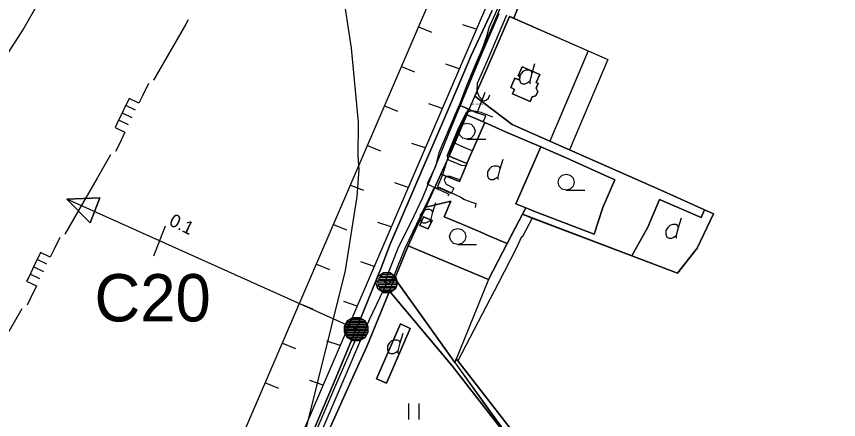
# Model space of a CAD drawing. Extents: x -645676 to -642474, y -1077513 to -1072613.
# Drawn here: x -643719.5 to -643337.9, y -1075036 to -1074848.6 of the extents above; entities that cross this region are included whole.
import ezdxf

# ---------------------------------------------------------------- set-up
doc = ezdxf.new("R2010")
doc.units = 0
for name, color, linetype in [('KN', 7, 'Continuous'), ('KULTURY_STAV', 7, 'Continuous'), ('KULTURY_ZNACKY', 7, 'Continuous'), ('M_stn__komunikace', 7, 'Continuous'), ('NERESENE_POZEMKY', 7, 'Continuous'), ('Obvod_KP_', 7, 'Continuous'), ('OBVOD_PU', 7, 'Continuous'), ('P__kop___st_vaj_c_', 7, 'Continuous'), ('PC_NAVRH', 7, 'Continuous'), ('PC_POPIS_NAVRH', 7, 'Continuous'), ('PC_STAN_NAVRH', 7, 'Continuous'), ('PC_STAN_STAV', 7, 'Continuous'), ('PC_STAV', 7, 'Continuous'), ('PLYNOVOD', 7, 'Continuous'), ('SDELOVACI', 7, 'Continuous'), ('USES_BK_NAVRH', 7, 'Continuous'), ('VRSTEVNICE', 7, 'Continuous')]:
    doc.layers.add(name, color=color, linetype=linetype)

# ---------------------------------------------------------------- blocks, each defined once
blk = doc.blocks.new('$437')
blk.add_lwpolyline([(0.15, 0.48), (0.4, 0.3), (0.5, 0.01), (0.4, -0.28), (0.15, -0.46), (-0.16, -0.46), (-0.41, -0.28), (-0.51, 0.01), (-0.41, 0.3), (-0.16, 0.48), (0.15, 0.48), (0.2, 0.4), (-0.2, 0.4), (-0.31, 0.32), (0.31, 0.32), (0.36, 0.24), (-0.36, 0.24), (-0.39, 0.16), (0.4, 0.16), (0.45, 0.08), (-0.43, 0.08), (-0.43, 0), (0.45, 0), (0.45, -0.08), (-0.43, -0.08), (-0.38, -0.16), (0.4, -0.16), (0.37, -0.24), (-0.35, -0.24), (-0.29, -0.32), (0.31, -0.32), (0.21, -0.4), (-0.19, -0.4)])
blk = doc.blocks.new('$406')
blk.add_lwpolyline([(-0.19, 0.72), (0.2, 0.72), (0.54, 0.53), (0.73, 0.19), (0.73, -0.2), (0.54, -0.54), (0.2, -0.73), (-0.19, -0.73), (-0.53, -0.54), (-0.72, -0.2), (-0.72, 0.19), (-0.53, 0.53), (-0.2, 0.72), (-0.28, 0.64), (0.28, 0.64), (0.44, 0.56), (-0.44, 0.56), (-0.52, 0.48), (0.52, 0.48), (0.56, 0.4), (-0.55, 0.4), (-0.6, 0.32), (0.6, 0.32), (0.68, 0.24), (-0.59, 0.24), (-0.65, 0.24), (-0.68, 0.16), (0.59, 0.16), (0.68, 0.16), (0.68, 0.08), (-0.59, 0.08), (-0.68, 0.08), (-0.68, 0), (0.59, 0), (0.68, 0), (0.68, -0.08), (-0.59, -0.08), (-0.68, -0.08), (-0.68, -0.16), (0.59, -0.16), (0.68, -0.16), (0.65, -0.24), (-0.62, -0.24), (-0.65, -0.24), (-0.6, -0.32), (0.6, -0.32), (0.56, -0.4), (-0.55, -0.4), (-0.52, -0.48), (0.52, -0.48), (0.44, -0.56), (-0.44, -0.56), (-0.28, -0.64), (0.28, -0.64), (-0.02, -0.69)])
blk = doc.blocks.new('$944')
blk.add_line((0, 1.5), (0, -1.5))
blk = doc.blocks.new('$920')
for points in [[(0, 0), (-2.8, 1.25), (-2.8, -1.25), (0, 0)], [(-2.8, 1.25), (0, 0), (-2.8, -1.25), (-2.8, 1.25)]]:
    blk.add_lwpolyline(points)
blk = doc.blocks.new('3$0400')
blk.add_lwpolyline([(0, 0), (-0.38, 0.1), (-0.65, 0.38), (-0.75, 0.75), (-0.65, 1.12), (-0.38, 1.4), (0, 1.5), (0.38, 1.4), (0.65, 1.12), (0.75, 0.75), (0.65, 0.38), (0.38, 0.1), (0, 0), (1.75, 0)])
blk = doc.blocks.new('$431')
blk.add_line((0.63, 0.99), (0.9, 1.89))
blk.add_lwpolyline([(0.45, 0), (0.45, 0.27), (0.63, 0.99), (0.54, 1.17), (0.36, 1.26), (0.09, 1.26), (-0.18, 1.17), (-0.36, 0.99), (-0.54, 0.72), (-0.54, 0.36), (-0.45, 0.09), (-0.27, 0), (0, 0), (0.18, 0.09), (0.45, 0.27)])
blk = doc.blocks.new('3$0600')
for p, q in [((-0.5, 1.5), (-0.5, 0)), ((0.5, 0), (0.5, 1.5))]:
    blk.add_line(p, q)
blk = doc.blocks.new('2$1030')
blk.add_line((0, 0), (0, -0.5))
blk = doc.blocks.new('6$3520')
for p, q in [((-0.76, 0), (-0.76, -1)), ((0, -1), (0, 0)), ((0.76, 0), (0.76, -1))]:
    blk.add_line(p, q)
blk.add_lwpolyline([(-3.5, 0), (-2.23, 0), (-1.48, 0), (-1.48, -1), (-0.21, -1), (1.06, -1), (1.5, -1), (1.5, 0), (2.77, 0), (3.5, 0)])

msp = doc.modelspace()

# ---------------------------------------------------------------- linework, layer by layer
at = {"layer": 'KN'}
msp.add_lwpolyline([(-643687.88, -1074804.66), (-643716.17, -1074854.15), (-643740.1, -1074891.11)], dxfattribs=at)
at = {"layer": 'KULTURY_STAV'}
for points in [[(-643478.45, -1074823.5), (-643488.73, -1074849.53), (-643490.75, -1074848.65), (-643500.55, -1074871.65), (-643506.75, -1074885.77), (-643489.5, -1074898.81), (-643471.96, -1074906.61), (-643462.8, -1074910.67), (-643419.43, -1074929.92), (-643400.22, -1074938.56), (-643401.77, -1074942.08), (-643421.02, -1074933.66), (-643426.53, -1074946.56), (-643432.36, -1074957.15), (-643433.93, -1074959.91), (-643480.12, -1074942.36), (-643484.72, -1074940.61), (-643483.17, -1074937.63), (-643478.59, -1074939.48), (-643451.33, -1074949.84), (-643447.33, -1074937.5), (-643441.73, -1074924.6), (-643464.34, -1074914.32), (-643476.16, -1074909.27), (-643492.61, -1074902.23), (-643502.18, -1074897.96), (-643510.44, -1074894.34), (-643518.71, -1074913.6), (-643510.41, -1074917.06), (-643510.79, -1074917.94), (-643513.96, -1074925.32), (-643522.51, -1074921.95), (-643529.49, -1074937.27), (-643537.7, -1074955.3), (-643543.93, -1074970.42), (-643527.22, -1074993.86), (-643516.08, -1075009.48), (-643515.41, -1075007.84), (-643514.63, -1075008.76), (-643478.55, -1075055.17)], [(-643478.55, -1075055.17), (-643514.63, -1075008.76), (-643515.41, -1075007.84), (-643516.08, -1075009.48), (-643527.22, -1074993.86), (-643543.93, -1074970.42), (-643537.7, -1074955.3), (-643500.46, -1074970.88), (-643491.76, -1074954.15), (-643489.24, -1074949.31), (-643484.72, -1074940.61), (-643480.12, -1074942.36), (-643433.93, -1074959.91), (-643412.65, -1074967.96), (-643403.55, -1074956.38), (-643396.05, -1074940.35), (-643400.22, -1074938.56), (-643419.43, -1074929.92), (-643462.8, -1074910.67), (-643471.96, -1074906.61), (-643489.5, -1074898.81), (-643506.75, -1074885.77), (-643500.55, -1074871.65), (-643490.75, -1074848.65), (-643488.73, -1074849.53), (-643478.45, -1074823.5)], [(-643582.48, -1075042.91), (-643572.34, -1075019.19), (-643561.84, -1074993.96), (-643561.59, -1074993.34), (-643560.36, -1074990.3), (-643550.3, -1074965.44), (-643546.14, -1074954.43), (-643535.97, -1074931.14), (-643530.69, -1074918.84), (-643521.31, -1074896.96), (-643514.06, -1074879.93), (-643508.45, -1074866.74), (-643498.78, -1074845.95)], [(-643498.78, -1074845.95), (-643508.45, -1074866.74), (-643514.06, -1074879.93), (-643521.31, -1074896.96), (-643530.69, -1074918.84), (-643535.97, -1074931.14), (-643546.14, -1074954.43), (-643550.3, -1074965.44), (-643560.36, -1074990.3), (-643561.59, -1074993.34), (-643561.84, -1074993.96), (-643572.34, -1075019.19), (-643582.48, -1075042.91)], [(-643484.76, -1074872.03), (-643476.64, -1074875.64), (-643478.27, -1074879.34), (-643477.37, -1074879.76), (-643478.33, -1074881.98), (-643477.51, -1074883.52), (-643478.43, -1074885.57), (-643480.13, -1074886.01), (-643481.09, -1074888.2), (-643489.25, -1074884.57), (-643488.34, -1074882.55), (-643489.82, -1074881.88), (-643490.11, -1074881.71), (-643488.19, -1074877.39), (-643486.42, -1074878.19), (-643485.76, -1074876.72), (-643486.64, -1074876.3), (-643484.76, -1074872.03)], [(-643484.76, -1074872.03), (-643486.64, -1074876.3), (-643485.76, -1074876.72), (-643486.42, -1074878.19), (-643488.19, -1074877.39), (-643490.11, -1074881.71), (-643489.82, -1074881.88), (-643488.34, -1074882.55), (-643489.25, -1074884.57), (-643481.09, -1074888.2), (-643480.13, -1074886.01), (-643478.43, -1074885.57), (-643477.51, -1074883.52), (-643478.33, -1074881.98), (-643477.37, -1074879.76), (-643478.27, -1074879.34), (-643476.64, -1074875.64), (-643484.76, -1074872.03)], [(-643510.44, -1074894.34), (-643502.18, -1074897.96), (-643510.41, -1074917.06), (-643518.71, -1074913.6), (-643510.44, -1074894.34)], [(-643502.18, -1074897.96), (-643492.61, -1074902.23), (-643476.16, -1074909.27), (-643487.7, -1074935.8), (-643483.17, -1074937.63), (-643484.72, -1074940.61), (-643489.24, -1074949.31), (-643491.76, -1074954.15), (-643500.24, -1074950.57), (-643504.01, -1074948.97), (-643513.15, -1074945.07), (-643520.99, -1074941.73), (-643517.86, -1074934.5), (-643529.49, -1074937.27), (-643522.51, -1074921.95), (-643513.96, -1074925.32), (-643510.79, -1074917.94), (-643510.41, -1074917.06), (-643502.18, -1074897.96)], [(-643476.16, -1074909.27), (-643464.34, -1074914.32), (-643441.73, -1074924.6), (-643447.33, -1074937.5), (-643451.33, -1074949.84), (-643478.59, -1074939.48), (-643483.17, -1074937.63), (-643487.7, -1074935.8), (-643476.16, -1074909.27)], [(-643517.86, -1074934.5), (-643520.99, -1074941.73), (-643513.15, -1074945.07), (-643504.01, -1074948.97), (-643500.24, -1074950.57), (-643491.76, -1074954.15), (-643500.46, -1074970.88), (-643537.7, -1074955.3), (-643529.49, -1074937.27), (-643517.86, -1074934.5)], [(-643421.02, -1074933.66), (-643401.77, -1074942.08), (-643400.22, -1074938.56), (-643396.05, -1074940.35), (-643403.55, -1074956.38), (-643412.65, -1074967.96), (-643433.93, -1074959.91), (-643432.36, -1074957.15), (-643426.53, -1074946.56), (-643421.02, -1074933.66)], [(-643530.53, -1074941.76), (-643532.27, -1074945.74), (-643528.4, -1074947.43), (-643526.63, -1074943.52), (-643530.53, -1074941.76)], [(-643530.53, -1074941.76), (-643526.63, -1074943.52), (-643528.4, -1074947.43), (-643532.27, -1074945.74), (-643530.53, -1074941.76)], [(-643546.39, -1074976.36), (-643517.29, -1075011.03), (-643481.44, -1075057.16), (-643466.38, -1075082.52), (-643468.64, -1075087.39), (-643538.17, -1075056.97), (-643574.53, -1075041.03), (-643562.74, -1075014.92), (-643556.97, -1075002.06), (-643546.39, -1074976.36)], [(-643481.44, -1075057.16), (-643517.29, -1075011.03), (-643546.39, -1074976.36), (-643556.97, -1075002.06), (-643562.74, -1075014.92), (-643574.53, -1075041.03)], [(-643541.28, -1074991.51), (-643536.72, -1074993.6), (-643547.78, -1075019.06), (-643552.38, -1075017.06), (-643541.28, -1074991.51)], [(-643541.28, -1074991.51), (-643552.38, -1075017.06), (-643547.78, -1075019.06), (-643536.72, -1074993.6), (-643541.28, -1074991.51)]]:
    msp.add_lwpolyline(points, dxfattribs=at)
at = {"layer": 'M_stn__komunikace'}
for p, q in [((-643504.52, -1074868.25), (-643495.41, -1074847.21)), ((-643492.01, -1074848.09), (-643501.11, -1074869.21)), ((-643517.08, -1074898.92), (-643504.52, -1074868.25)), ((-643501.11, -1074869.21), (-643505.65, -1074879.85)), ((-643505.65, -1074879.85), (-643505.81, -1074883.27)), ((-643505.81, -1074883.27), (-643504.93, -1074885.72)), ((-643504.93, -1074885.72), (-643502.79, -1074887.96)), ((-643501.5, -1074887.58), (-643500.49, -1074886.61)), ((-643500.49, -1074886.61), (-643499.78, -1074885.02)), ((-643502.79, -1074887.96), (-643501.5, -1074887.58)), ((-643510.73, -1074893.28), (-643514.35, -1074900.43)), ((-643507.98, -1074892.49), (-643510.73, -1074893.28)), ((-643503.89, -1074893.23), (-643507.98, -1074892.49)), ((-643498.49, -1074895.39), (-643503.89, -1074893.23)), ((-643530.87, -1074932.87), (-643517.08, -1074898.92)), ((-643514.35, -1074900.43), (-643519.67, -1074913.34)), ((-643519.67, -1074913.34), (-643519.27, -1074915.14)), ((-643519.27, -1074915.14), (-643513.1, -1074917.75)), ((-643513.1, -1074917.75), (-643510.8, -1074917.94)), ((-643520.23, -1074923.09), (-643521.03, -1074924.74)), ((-643521.03, -1074924.74), (-643520.05, -1074926.62)), ((-643518.17, -1074923.08), (-643520.23, -1074923.09)), ((-643513.7, -1074924.62), (-643518.17, -1074923.08)), ((-643526.04, -1074929.03), (-643528.53, -1074934.28)), ((-643525.09, -1074928.38), (-643526.04, -1074929.03)), ((-643522.78, -1074928.62), (-643525.09, -1074928.38)), ((-643517.76, -1074930.96), (-643522.78, -1074928.62)), ((-643520.05, -1074926.62), (-643516.56, -1074928.41)), ((-643516.56, -1074928.41), (-643517.76, -1074930.96)), ((-643536.26, -1074944.29), (-643530.87, -1074932.87)), ((-643528.53, -1074934.28), (-643533.84, -1074945.22)), ((-643542, -1074955.5), (-643536.26, -1074944.29)), ((-643533.84, -1074945.22), (-643539.23, -1074956.48)), ((-643548.53, -1074972.03), (-643542, -1074955.5)), ((-643539.23, -1074956.48), (-643544.71, -1074970.05)), ((-643544.71, -1074970.05), (-643546.65, -1074973.09)), ((-643546.65, -1074973.09), (-643548.53, -1074972.03))]:
    msp.add_line(p, q, dxfattribs=at)
at = {"layer": 'NERESENE_POZEMKY'}
for points in [[(-643574.53, -1075041.03), (-643562.74, -1075014.92), (-643556.97, -1075002.06), (-643546.39, -1074976.36), (-643545.25, -1074973.62), (-643543.93, -1074970.42), (-643537.7, -1074955.3), (-643529.49, -1074937.27), (-643522.51, -1074921.95), (-643518.71, -1074913.6), (-643510.44, -1074894.34), (-643506.75, -1074885.77), (-643500.55, -1074871.65), (-643490.75, -1074848.65)], [(-643490.75, -1074848.65), (-643488.73, -1074849.53), (-643454.15, -1074864.58), (-643445.05, -1074868.59), (-643462.8, -1074910.67), (-643419.43, -1074929.92), (-643400.22, -1074938.56), (-643396.05, -1074940.35), (-643403.55, -1074956.38), (-643412.65, -1074967.96), (-643433.93, -1074959.91), (-643480.12, -1074942.36), (-643484.74, -1074951.23), (-643485.16, -1074951.12), (-643487.37, -1074956.17), (-643495.99, -1074972.78), (-643514.63, -1075008.76), (-643478.55, -1075055.17)]]:
    msp.add_lwpolyline(points, dxfattribs=at)
at = {"layer": 'Obvod_KP_'}
for points in [[(-643730.15, -1074676.99), (-643712.93, -1074647.72), (-643703.01, -1074630.92), (-643676.88, -1074645.92), (-643687.98, -1074664.87), (-643699.6, -1074684.03), (-643658.16, -1074692.76), (-643652.49, -1074694.77), (-643634.51, -1074700.94), (-643641.64, -1074716), (-643663.42, -1074760), (-643687.88, -1074804.66), (-643716.17, -1074854.15), (-643740.1, -1074891.11)], [(-643574.53, -1075041.03), (-643562.74, -1075014.92), (-643556.97, -1075002.06), (-643545.25, -1074973.62), (-643543.93, -1074970.42), (-643537.7, -1074955.3), (-643529.49, -1074937.27), (-643522.51, -1074921.95), (-643518.71, -1074913.6), (-643517.89, -1074911.68), (-643510.44, -1074894.34), (-643506.75, -1074885.77), (-643500.55, -1074871.65), (-643490.75, -1074848.65), (-643454.15, -1074864.58), (-643463.9, -1074887.67), (-643471.96, -1074906.61), (-643419.43, -1074929.92), (-643400.22, -1074938.56), (-643396.05, -1074940.35), (-643403.55, -1074956.38), (-643412.65, -1074967.96), (-643433.93, -1074959.91), (-643484.72, -1074940.61), (-643491.76, -1074954.15), (-643500.46, -1074970.88), (-643516.08, -1075009.48), (-643490.94, -1075044.62)]]:
    msp.add_lwpolyline(points, dxfattribs=at)
at = {"layer": 'OBVOD_PU'}
for points in [[(-643730.15, -1074676.99), (-643712.93, -1074647.72), (-643703.01, -1074630.92), (-643676.88, -1074645.92), (-643687.98, -1074664.87), (-643699.6, -1074684.03), (-643658.16, -1074692.76), (-643652.49, -1074694.77), (-643634.51, -1074700.94), (-643641.64, -1074716), (-643663.42, -1074760), (-643687.88, -1074804.66), (-643716.17, -1074854.15), (-643740.1, -1074891.11)], [(-643574.53, -1075041.03), (-643562.74, -1075014.92), (-643556.97, -1075002.06), (-643545.25, -1074973.62), (-643543.93, -1074970.42), (-643537.7, -1074955.3), (-643529.49, -1074937.27), (-643518.71, -1074913.6), (-643517.89, -1074911.68), (-643510.44, -1074894.34), (-643506.75, -1074885.77), (-643500.55, -1074871.65), (-643490.75, -1074848.65)], [(-643490.75, -1074848.65), (-643454.15, -1074864.58), (-643471.96, -1074906.61), (-643419.43, -1074929.92), (-643400.22, -1074938.56), (-643396.05, -1074940.35), (-643403.55, -1074956.38), (-643412.65, -1074967.96), (-643484.72, -1074940.61), (-643491.76, -1074954.15), (-643500.46, -1074970.88), (-643516.08, -1075009.48), (-643462, -1075084.28)]]:
    msp.add_lwpolyline(points, dxfattribs=at)
at = {"layer": 'P__kop___st_vaj_c_'}
msp.add_lwpolyline([(-643616.01, -1075125.08), (-643595.06, -1075075.72), (-643571.29, -1075019.94), (-643560.26, -1074994.78)], dxfattribs=at)
at = {"layer": 'PC_NAVRH'}
msp.add_line((-643561.84, -1074993.96), (-643696.1, -1074933.6), dxfattribs=at)
at = {"layer": 'PC_STAV'}
msp.add_lwpolyline([(-643547.63, -1074972.51), (-643555.63, -1074989.35), (-643604.37, -1075103.28), (-643624.41, -1075149.11)], dxfattribs=at)
at = {"layer": 'PLYNOVOD'}
for p, q in [((-643494.35, -1074843.3), (-643510.56, -1074880.72)), ((-643510.56, -1074880.72), (-643512.78, -1074887.6)), ((-643505.26, -1074892.23), (-643503.01, -1074886.72)), ((-643503.01, -1074886.72), (-643501.9, -1074883.89)), ((-643513.97, -1074889.93), (-643515.2, -1074892.37)), ((-643512.78, -1074887.6), (-643513.97, -1074889.93)), ((-643513.97, -1074889.93), (-643513.01, -1074890.32)), ((-643513.01, -1074890.32), (-643512.02, -1074890.72)), ((-643512.02, -1074890.72), (-643505.8, -1074893.51)), ((-643505.8, -1074893.51), (-643512.02, -1074890.72)), ((-643515.2, -1074892.37), (-643523.45, -1074912.05)), ((-643505.8, -1074893.51), (-643505.26, -1074892.23)), ((-643501.66, -1074894.88), (-643505.8, -1074893.51)), ((-643502.1, -1074895.89), (-643501.66, -1074894.88)), ((-643502.85, -1074897.64), (-643502.1, -1074895.89)), ((-643523.45, -1074912.05), (-643525.1, -1074918.34)), ((-643525.1, -1074918.34), (-643528.92, -1074926.5)), ((-643528.92, -1074926.5), (-643524.59, -1074928.54)), ((-643524.59, -1074928.54), (-643523.41, -1074929.09)), ((-643523.41, -1074929.09), (-643523.05, -1074929.26)), ((-643523.05, -1074929.26), (-643518.88, -1074931.21)), ((-643519.09, -1074931.8), (-643519.28, -1074932.24)), ((-643518.88, -1074931.21), (-643519.09, -1074931.8))]:
    msp.add_line(p, q, dxfattribs=at)
for points in [[(-643473.17, -1074784.29), (-643471.97, -1074786.75), (-643471.39, -1074788.95), (-643471.45, -1074790.05), (-643483.17, -1074817.28), (-643494.35, -1074843.3), (-643510.56, -1074880.72), (-643512.78, -1074887.6), (-643513.97, -1074889.93)], [(-643639.81, -1074850.16), (-643640.99, -1074852.27), (-643655.94, -1074878.28)], [(-643513.97, -1074889.93), (-643515.2, -1074892.37), (-643523.45, -1074912.05), (-643525.1, -1074918.34), (-643528.92, -1074926.5), (-643524.59, -1074928.54)], [(-643513.97, -1074889.93), (-643513.01, -1074890.32), (-643512.02, -1074890.72)], [(-643675.88, -1074912.96), (-643682.11, -1074923.8), (-643697.07, -1074949.81)], [(-643717.01, -1074984.48), (-643783.07, -1075099.35), (-643798.43, -1075125.12)]]:
    msp.add_lwpolyline(points, dxfattribs=at)
at = {"layer": 'SDELOVACI'}
for points in [[(-643516.67, -1074907.25), (-643515.04, -1074903.21), (-643511.46, -1074895.22), (-643509.64, -1074891.94), (-643513.87, -1074889.85), (-643512.75, -1074887), (-643510.3, -1074880.36), (-643506.66, -1074871.49), (-643503.28, -1074863.55), (-643501.11, -1074857.43), (-643500.16, -1074853.79), (-643495.79, -1074844.24), (-643492.07, -1074835.9), (-643488.14, -1074826.84), (-643481.47, -1074812.29), (-643477.13, -1074801.57), (-643473.43, -1074792.52), (-643472.22, -1074786.75)], [(-643516.67, -1074907.25), (-643515.04, -1074903.21), (-643511.46, -1074895.22), (-643509.64, -1074891.94), (-643513.87, -1074889.85), (-643512.75, -1074887), (-643510.3, -1074880.36), (-643506.66, -1074871.49), (-643503.28, -1074863.55), (-643501.11, -1074857.43), (-643500.16, -1074853.79), (-643495.79, -1074844.24), (-643492.07, -1074835.9), (-643488.14, -1074826.84), (-643481.47, -1074812.29), (-643477.13, -1074801.57), (-643473.43, -1074792.52), (-643472.22, -1074786.75)], [(-643516.67, -1074907.25), (-643519.55, -1074913.71), (-643519.09, -1074914.27)], [(-643516.67, -1074907.25), (-643519.55, -1074913.71), (-643519.09, -1074914.27)], [(-643516.67, -1074907.25), (-643511.8, -1074909.35), (-643508.91, -1074910.6), (-643507.73, -1074910.79)], [(-643516.67, -1074907.25), (-643511.8, -1074909.35), (-643508.91, -1074910.6), (-643507.73, -1074910.79)], [(-643519.09, -1074914.27), (-643519.43, -1074914.81), (-643521.8, -1074922.23), (-643524.05, -1074927.63), (-643515.9, -1074931.41), (-643513.34, -1074932.65), (-643511.58, -1074933.69), (-643508.16, -1074935.02), (-643506.28, -1074935.64), (-643506.67, -1074937.51)], [(-643519.09, -1074914.27), (-643519.43, -1074914.81), (-643521.8, -1074922.23), (-643524.05, -1074927.63), (-643515.9, -1074931.41), (-643513.34, -1074932.65), (-643511.58, -1074933.69), (-643508.16, -1074935.02), (-643506.28, -1074935.64), (-643506.67, -1074937.51)]]:
    msp.add_lwpolyline(points, dxfattribs=at)
at = {"layer": 'USES_BK_NAVRH'}
msp.add_lwpolyline([(-643140.05, -1074334.77), (-643371.48, -1074723.77), (-643386.93, -1074710.69), (-643471.56, -1074774.24), (-643586.65, -1075041.85), (-643614.85, -1075044.14), (-643491.9, -1074758.24), (-643387.13, -1074679.58), (-643365.02, -1074664.02), (-643154.25, -1074308.76)], dxfattribs=at)
at = {"layer": 'VRSTEVNICE'}
msp.add_lwpolyline([(-643592.44, -1075070.19), (-643566.8, -1074966.79), (-643561.39, -1074932.32), (-643560.4, -1074919.79), (-643560.97, -1074913.52), (-643560.82, -1074897.86), (-643563.96, -1074863.39), (-643571.08, -1074816.39), (-643575.63, -1074797.59), (-643580.48, -1074785.06), (-643595.57, -1074755.72), (-643606.4, -1074738.63), (-643613.66, -1074730.09), (-643623.35, -1074721.54), (-643624.77, -1074717.41), (-643624.48, -1074710.29), (-643625.62, -1074705.02), (-643627.19, -1074702.17), (-643648.13, -1074681.95), (-643661.09, -1074666.57), (-643673.05, -1074649.9), (-643691.28, -1074616.72)], dxfattribs=at)

# ---------------------------------------------------------------- block references
at = {"layer": 'KULTURY_ZNACKY', "xscale": 5, "yscale": 5}
for name, p in [('$431', (-643483.37, -1074879.91)), ('3$0400', (-643510.42, -1074905.7)), ('$431', (-643498.18, -1074924.47)), ('3$0400', (-643464.39, -1074929.46)), ('$431', (-643529.45, -1074944.61)), ('$431', (-643415.35, -1074951.69)), ('3$0400', (-643514.71, -1074954.66)), ('$431', (-643544.55, -1075005.33)), ('3$0600', (-643535.07, -1075035.99))]:
    msp.add_blockref(name, p, dxfattribs=at)
at = {"layer": 'PC_STAN_NAVRH', "xscale": 4.999999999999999, "yscale": 5, "rotation": 158.512054}
for name, p in [('$920', (-643696.1, -1074933.6)), ('$944', (-643653.05, -1074952.96))]:
    msp.add_blockref(name, p, dxfattribs=at)
at = {"layer": 'PC_STAN_NAVRH', "xscale": 7.5, "yscale": 7.5}
msp.add_blockref('$406', (-643561.84, -1074993.96), dxfattribs=at)
at = {"layer": 'PC_STAN_STAV', "xscale": 10, "yscale": 10}
msp.add_blockref('$437', (-643547.63, -1074972.51), dxfattribs=at)
at = {"layer": 'PLYNOVOD', "xscale": 5}
for p, yscale, rotation in [((-643665.91, -1074895.62), 4.999999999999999, -115.702375), ((-643707.04, -1074967.14), 5.000000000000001, -115.71302200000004)]:
    msp.add_blockref('6$3520', p, dxfattribs=dict(at, yscale=yscale, rotation=rotation))
at = {"layer": 'USES_BK_NAVRH', "xscale": 13}
for p, yscale, rotation in [((-643506.13, -1074854.62), 13.000000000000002, -108.96340500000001), ((-643532.87, -1074853.52), 13, 67.895018), ((-643540.78, -1074871.9), 13, 67.895018), ((-643514.03, -1074872.99), 13.000000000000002, -108.96340500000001), ((-643548.68, -1074890.27), 13, 67.895018), ((-643521.93, -1074891.37), 13.000000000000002, -108.96340500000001), ((-643556.58, -1074908.64), 13, 67.895018), ((-643529.84, -1074909.74), 13.000000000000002, -108.96340500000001), ((-643564.48, -1074927.01), 13, 67.895018), ((-643537.74, -1074928.11), 13.000000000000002, -108.96340500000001), ((-643545.64, -1074946.49), 13.000000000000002, -108.96340500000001), ((-643572.38, -1074945.39), 13, 67.895018), ((-643553.54, -1074964.86), 13.000000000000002, -108.96340500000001), ((-643580.28, -1074963.76), 13, 67.895018), ((-643588.18, -1074982.13), 13, 67.895018), ((-643561.44, -1074983.23), 13.000000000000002, -108.96340500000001), ((-643596.08, -1075000.51), 13, 67.895018), ((-643569.34, -1075001.6), 13.000000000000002, -108.96340500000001), ((-643603.98, -1075018.88), 13, 67.895018), ((-643577.24, -1075019.98), 13.000000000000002, -108.96340500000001)]:
    msp.add_blockref('2$1030', p, dxfattribs=dict(at, yscale=yscale, rotation=rotation))

# ---------------------------------------------------------------- texts
at = {"layer": 'M_stn__komunikace'}
msp.add_text('asf. cesta', height=1, dxfattribs=at).set_placement((-643509.01, -1074889.75))
at = {"layer": 'PC_POPIS_NAVRH'}
msp.add_text('C20', height=22, dxfattribs=at).set_placement((-643683.31, -1074990.39))
at = {"layer": 'PC_STAN_NAVRH'}
msp.add_text('0.1', height=6, rotation=333.92, dxfattribs=at).set_placement((-643649.15, -1074945.45))

doc.saveas('drawing.dxf')
